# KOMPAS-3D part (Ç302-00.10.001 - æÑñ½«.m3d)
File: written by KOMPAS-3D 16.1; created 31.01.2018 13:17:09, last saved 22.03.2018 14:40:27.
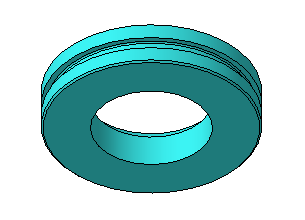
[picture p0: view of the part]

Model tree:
1. Эскиз:1
2. Операция вращения:1
     Угол 1 = 360
3. Скругление:1
     Радиус = 0.4
4. Фаска:1  (labels: Фторопласт-4  ГОСТ 10007-80 Е)
     Угол = 45; Длина 1 = 0.5; Длина 2 = 0.5

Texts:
  Линейный размер с обрывом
